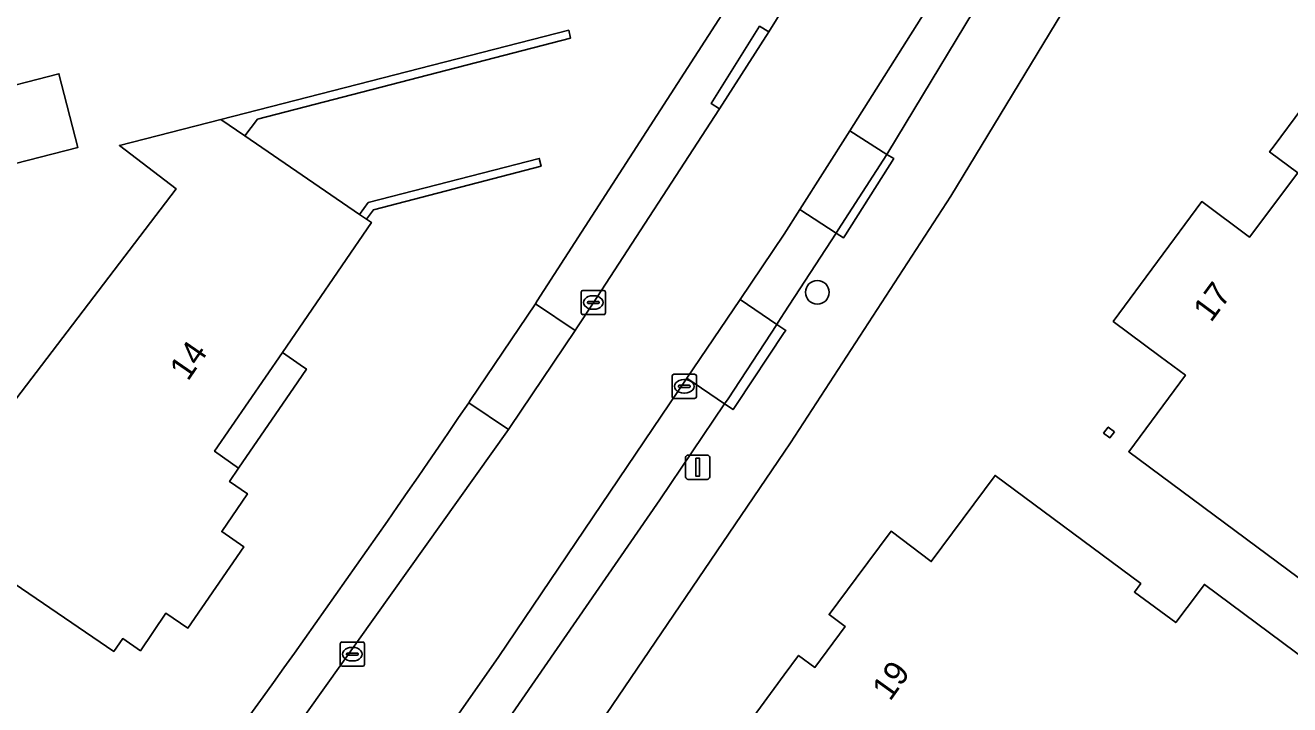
# Model space of a CAD drawing. Extents: x 158835 to 160077, y 386387 to 387778.
# Drawn here: x 159468.8 to 159520.8, y 386661.1 to 386689.1 of the extents above; entities that cross this region are included whole.
import ezdxf

# ---------------------------------------------------------------- set-up
doc = ezdxf.new("R2010")
doc.units = 0
for name, color, linetype in [('IMGEO_Boom', 7, 'Continuous'), ('IMGEO_Erf', 7, 'Continuous'), ('IMGEO_Kolk', 7, 'Continuous'), ('IMGEO_Lichtmast', 7, 'Continuous'), ('IMGEO_Muur', 7, 'Continuous'), ('IMGEO_Pand', 7, 'Continuous'), ('IMGEO_Pand_nummerreeks', 7, 'Continuous'), ('IMGEO_Pand_overbouw', 7, 'Continuous'), ('IMGEO_Parkeervlak_open', 7, 'Continuous'), ('IMGEO_Rijbaan_lokaal_gesloten', 7, 'Continuous'), ('IMGEO_Voetpad_open', 7, 'Continuous')]:
    doc.layers.add(name, color=color, linetype=linetype)

msp = doc.modelspace()

# ---------------------------------------------------------------- linework, layer by layer
at = {"layer": 'IMGEO_Boom'}
msp.add_circle((159501.359, 386678.098), 0.489, dxfattribs=at)
at = {"layer": 'IMGEO_Erf'}
for points in [[(159523.936, 386720.207), (159523.989, 386717.606), (159523.81, 386715.012), (159523.4, 386712.444), (159522.762, 386709.923), (159521.901, 386707.468), (159520.825, 386705.101), (159506.854, 386682.053), (159500.252, 386671.907), (159500, 386671.529), (159492.426, 386660.371), (159492.025, 386659.896), (159480.297, 386643.692), (159466.865, 386626.712)], [(159487.016, 386673.557), (159487.077, 386673.647), (159489.757, 386677.629), (159489.836, 386677.746), (159499.829, 386693.238), (159500, 386693.513), (159510.606, 386711.419), (159511.034, 386712.323), (159511.379, 386713.262), (159511.639, 386714.228), (159511.811, 386715.214), (159511.887, 386716.039), (159511.952, 386719.617)], [(159522.042, 386665.693), (159514.171, 386671.538), (159516.506, 386674.684), (159515.461, 386675.464), (159513.533, 386676.904), (159517.176, 386681.83), (159519.142, 386680.372), (159521.129, 386683.006), (159519.965, 386683.87), (159520.153, 386684.123), (159522.43, 386687.19)], [(159498.048, 386659.711), (159500, 386662.363), (159500.589, 386663.163), (159501.258, 386662.671), (159502.506, 386664.348), (159501.841, 386664.844), (159502.959, 386666.346), (159504.391, 386668.27), (159506.047, 386667.022), (159508.675, 386670.566), (159514.667, 386666.121), (159514.405, 386665.768), (159516.105, 386664.516), (159516.575, 386665.131), (159517.286, 386666.082), (159529.001, 386657.369)]]:
    msp.add_lwpolyline(points, dxfattribs=at)
for points in [[(159472.645, 386684.138), (159476.823, 386685.207), (159491.131, 386688.877), (159491.202, 386688.552), (159478.326, 386685.224), (159477.803, 386684.535), (159482.519, 386681.3), (159482.879, 386681.794), (159489.914, 386683.607), (159489.99, 386683.281), (159483.094, 386681.494), (159482.805, 386681.113), (159483.009, 386680.975), (159479.351, 386675.617), (159476.56, 386671.56), (159477.546, 386670.861), (159477.174, 386670.314), (159477.911, 386669.812), (159476.855, 386668.254), (159477.761, 386667.631), (159475.462, 386664.289), (159474.553, 386664.901), (159473.506, 386663.357), (159472.784, 386663.856), (159472.411, 386663.325), (159464.547, 386668.691), (159474.982, 386682.353)], [(159467.053, 386686.293), (159470.155, 386687.091), (159470.936, 386684.056), (159467.834, 386683.258)], [(159513.582, 386672.364), (159513.396, 386672.113), (159513.138, 386672.305), (159513.325, 386672.556)]]:
    msp.add_lwpolyline(points, close=True, dxfattribs=at)
msp.add_arc((159034.245, 386981.09), 547.337, 323.34107, 325.81472, dxfattribs=at)
at = {"layer": 'IMGEO_Kolk'}
for p, q in [((159491.717, 386678.179), (159492.569, 386678.179)), ((159491.642, 386677.253), (159491.642, 386678.105)), ((159491.901, 386677.673), (159491.901, 386677.685)), ((159492.339, 386677.636), (159491.941, 386677.636)), ((159491.944, 386677.722), (159492.342, 386677.722)), ((159492.13, 386677.959), (159492.155, 386677.959)), ((159492.385, 386677.685), (159492.385, 386677.673)), ((159492.643, 386678.105), (159492.643, 386677.253)), ((159492.569, 386677.179), (159491.717, 386677.179)), ((159492.153, 386677.399), (159492.128, 386677.399)), ((159495.384, 386673.805), (159495.384, 386674.657)), ((159495.459, 386674.731), (159496.311, 386674.731)), ((159495.872, 386674.511), (159495.897, 386674.511)), ((159496.385, 386674.657), (159496.385, 386673.805)), ((159495.643, 386674.225), (159495.643, 386674.237)), ((159496.081, 386674.188), (159495.683, 386674.188)), ((159495.686, 386674.274), (159496.084, 386674.274)), ((159496.127, 386674.237), (159496.127, 386674.225)), ((159496.311, 386673.731), (159495.459, 386673.731)), ((159495.895, 386673.951), (159495.87, 386673.951)), ((159481.727, 386662.789), (159481.727, 386663.641)), ((159481.802, 386663.715), (159482.654, 386663.715)), ((159482.728, 386663.641), (159482.728, 386662.789)), ((159481.986, 386663.209), (159481.986, 386663.221)), ((159482.424, 386663.172), (159482.026, 386663.172)), ((159482.029, 386663.258), (159482.427, 386663.258)), ((159482.215, 386663.495), (159482.24, 386663.495)), ((159482.47, 386663.221), (159482.47, 386663.209)), ((159482.654, 386662.715), (159481.802, 386662.715)), ((159482.238, 386662.935), (159482.213, 386662.935))]:
    msp.add_line(p, q, dxfattribs=at)
for points in [[(159491.717, 386678.179), (159492.569, 386678.179)], [(159491.642, 386677.253), (159491.642, 386678.105)], [(159492.643, 386678.105), (159492.643, 386677.253)], [(159492.569, 386677.179), (159491.717, 386677.179)], [(159495.384, 386673.805), (159495.384, 386674.657)], [(159495.459, 386674.731), (159496.311, 386674.731)], [(159496.385, 386674.657), (159496.385, 386673.805)], [(159496.311, 386673.731), (159495.459, 386673.731)], [(159481.727, 386662.789), (159481.727, 386663.641)], [(159481.802, 386663.715), (159482.654, 386663.715)], [(159482.728, 386663.641), (159482.728, 386662.789)], [(159482.654, 386662.715), (159481.802, 386662.715)]]:
    msp.add_lwpolyline(points, dxfattribs=at)
for centre, radius, start, end in [((159491.719, 386678.103), 0.0765, 91.552, 178.448), ((159491.719, 386678.103), 0.0765, 91.552, 178.448), ((159492.567, 386678.103), 0.0765, 1.552, 88.448), ((159492.567, 386678.103), 0.0765, 1.552, 88.448), ((159491.941, 386677.682), 0.0403, 85.8775, 175.7526), ((159491.938, 386677.672), 0.0366, 178.938, 274.7102), ((159492.342, 386677.679), 0.043, 264.8664, 352.4533), ((159492.346, 386677.684), 0.0386, 1.7309, 96.639), ((159491.719, 386677.255), 0.0765, 181.552, 268.448), ((159491.719, 386677.255), 0.0765, 181.552, 268.448), ((159492.567, 386677.255), 0.0765, 271.552, 358.448), ((159492.567, 386677.255), 0.0765, 271.552, 358.448), ((159495.461, 386674.655), 0.0765, 91.552, 178.448), ((159495.461, 386674.655), 0.0765, 91.552, 178.448), ((159496.309, 386674.655), 0.0765, 1.552, 88.448), ((159496.309, 386674.655), 0.0765, 1.552, 88.448), ((159495.683, 386674.234), 0.0403, 85.8775, 175.7526), ((159495.68, 386674.224), 0.0366, 178.938, 274.7102), ((159496.084, 386674.231), 0.043, 264.8664, 352.4533), ((159496.088, 386674.236), 0.0386, 1.7309, 96.639), ((159495.461, 386673.807), 0.0765, 181.552, 268.448), ((159495.461, 386673.807), 0.0765, 181.552, 268.448), ((159496.309, 386673.807), 0.0765, 271.552, 358.448), ((159496.309, 386673.807), 0.0765, 271.552, 358.448), ((159481.804, 386663.639), 0.0765, 91.552, 178.448), ((159481.804, 386663.639), 0.0765, 91.552, 178.448), ((159482.652, 386663.639), 0.0765, 1.552, 88.448), ((159482.652, 386663.639), 0.0765, 1.552, 88.448), ((159482.026, 386663.218), 0.0403, 85.8775, 175.7526), ((159482.023, 386663.208), 0.0366, 178.938, 274.7102), ((159482.427, 386663.215), 0.043, 264.8664, 352.4533), ((159482.431, 386663.22), 0.0386, 1.7309, 96.639), ((159481.804, 386662.791), 0.0765, 181.552, 268.448), ((159481.804, 386662.791), 0.0765, 181.552, 268.448), ((159482.652, 386662.791), 0.0765, 271.552, 358.448), ((159482.652, 386662.791), 0.0765, 271.552, 358.448)]:
    msp.add_arc(centre, radius, start, end, dxfattribs=at)
for centre, major_axis, ratio, start_param, end_param in [((159492.129, 386677.679), (-0.387, 0.002), 0.722429, 4.712389, 7.853982), ((159492.154, 386677.679), (-0.39, 0.002), 0.717154, 1.570796, 4.712389), ((159495.871, 386674.231), (-0.387, 0.002), 0.722429, 4.712389, 7.853982), ((159495.896, 386674.231), (-0.39, 0.002), 0.717154, 1.570796, 4.712389), ((159482.214, 386663.215), (-0.387, 0.002), 0.722429, 4.712389, 7.853982), ((159482.239, 386663.215), (-0.39, 0.002), 0.717154, 1.570796, 4.712389)]:
    msp.add_ellipse(centre, major_axis=major_axis, ratio=ratio, start_param=start_param, end_param=end_param, dxfattribs=at)
at = {"layer": 'IMGEO_Lichtmast'}
for p, q in [((159496.04, 386671.405), (159496.83, 386671.405)), ((159496.83, 386671.405), (159496.04, 386671.405)), ((159495.94, 386670.505), (159495.94, 386671.305)), ((159495.94, 386671.305), (159495.94, 386670.505)), ((159496.93, 386671.305), (159496.93, 386670.505)), ((159496.93, 386670.505), (159496.93, 386671.305)), ((159496.83, 386670.405), (159496.04, 386670.405)), ((159496.04, 386670.405), (159496.83, 386670.405))]:
    msp.add_line(p, q, dxfattribs=at)
msp.add_lwpolyline([(159496.36, 386671.28), (159496.51, 386671.28), (159496.51, 386670.53), (159496.36, 386670.53), (159496.36, 386671.28)], dxfattribs=at)
for centre, start, end in [((159496.04, 386671.305), 90, 180), ((159496.04, 386671.305), 90, 180), ((159496.83, 386671.305), 0, 90), ((159496.83, 386671.305), 360, 90), ((159496.04, 386670.505), 180, 270), ((159496.04, 386670.505), 180, 270), ((159496.83, 386670.505), 270, 0), ((159496.83, 386670.505), 270, 0)]:
    msp.add_arc(centre, 0.1, start, end, dxfattribs=at)
at = {"layer": 'IMGEO_Muur'}
for points in [[(159477.803, 386684.535), (159478.326, 386685.224), (159491.202, 386688.552), (159491.131, 386688.877), (159476.823, 386685.207)], [(159482.805, 386681.113), (159483.094, 386681.494), (159489.99, 386683.281), (159489.914, 386683.607), (159482.879, 386681.794), (159482.519, 386681.3)]]:
    msp.add_lwpolyline(points, close=True, dxfattribs=at)
at = {"layer": 'IMGEO_Pand'}
for points in [[(159467.053, 386686.293), (159467.834, 386683.258), (159470.936, 386684.056), (159470.155, 386687.091)], [(159522.43, 386687.19), (159520.153, 386684.123), (159519.965, 386683.87), (159521.129, 386683.006), (159519.142, 386680.372), (159517.176, 386681.83), (159513.533, 386676.904), (159515.461, 386675.464), (159516.506, 386674.684), (159514.171, 386671.538), (159522.042, 386665.693), (159525.422, 386670.2), (159523.707, 386671.486), (159527.613, 386676.695), (159533.54, 386672.251), (159529.173, 386666.427), (159533.385, 386663.269), (159540.934, 386673.397)], [(159483.009, 386680.975), (159482.805, 386681.113), (159482.519, 386681.3), (159477.803, 386684.535), (159476.823, 386685.207), (159472.645, 386684.138), (159474.982, 386682.353), (159464.547, 386668.691), (159472.411, 386663.325), (159472.784, 386663.856), (159473.506, 386663.357), (159474.553, 386664.901), (159475.462, 386664.289), (159477.761, 386667.631), (159476.855, 386668.254), (159477.911, 386669.812), (159477.174, 386670.314), (159477.546, 386670.861), (159476.56, 386671.56), (159479.351, 386675.617)], [(159513.582, 386672.364), (159513.325, 386672.556), (159513.138, 386672.305), (159513.396, 386672.113)]]:
    msp.add_lwpolyline(points, close=True, dxfattribs=at)
msp.add_lwpolyline([(159529.001, 386657.369), (159517.286, 386666.082), (159516.575, 386665.131), (159516.105, 386664.516), (159514.405, 386665.768), (159514.667, 386666.121), (159508.675, 386670.566), (159506.047, 386667.022), (159504.391, 386668.27), (159502.959, 386666.346), (159501.841, 386664.844), (159502.506, 386664.348), (159501.258, 386662.671), (159500.589, 386663.163), (159500, 386662.363), (159498.048, 386659.711)], dxfattribs=at)
at = {"layer": 'IMGEO_Pand_overbouw'}
msp.add_lwpolyline([(159477.546, 386670.861), (159479.98, 386674.411), (159480.341, 386674.941), (159480.078, 386675.12), (159479.351, 386675.617), (159476.56, 386671.56)], close=True, dxfattribs=at)
at = {"layer": 'IMGEO_Parkeervlak_open'}
for points in [[(159518.046, 386706.634), (159519.101, 386708.953), (159517.443, 386709.606), (159517.076, 386708.722), (159516.302, 386707.245), (159505.787, 386689.619), (159502.694, 386684.743), (159504.222, 386683.773), (159504.259, 386683.831)], [(159502.136, 386680.535), (159500.64, 386681.505), (159500, 386680.496), (159498.178, 386677.802), (159499.693, 386676.778), (159499.749, 386676.864), (159500, 386677.248)], [(159497.546, 386673.509), (159495.988, 386674.563), (159488.253, 386663.123), (159486.494, 386660.609), (159487.977, 386659.57), (159488.022, 386659.633), (159494.875, 386669.563)]]:
    msp.add_lwpolyline(points, close=True, dxfattribs=at)
at = {"layer": 'IMGEO_Rijbaan_lokaal_gesloten'}
for points in [[(159513.878, 386721.278), (159513.869, 386716.038), (159513.796, 386715.241), (159513.584, 386713.955), (159513.258, 386712.692), (159512.821, 386711.465), (159512.275, 386710.281), (159511.626, 386709.15), (159501.61, 386692.371), (159500.806, 386691.095), (159500, 386689.822), (159499.36, 386688.811), (159497.335, 386685.65), (159492.103, 386677.614), (159491.469, 386676.644), (159491.393, 386676.531), (159488.703, 386672.537), (159488.647, 386672.459), (159474.87, 386653.114), (159472.629, 386650.095), (159472.496, 386649.912), (159463.597, 386638.445)], [(159465.699, 386633.096), (159473.919, 386643.589), (159475.879, 386646.09), (159476.255, 386646.598), (159484.227, 386657.37), (159484.364, 386657.566), (159486.494, 386660.609), (159488.253, 386663.123), (159495.988, 386674.563), (159498.178, 386677.802), (159500, 386680.496), (159500.64, 386681.505), (159502.694, 386684.743), (159505.787, 386689.619), (159516.302, 386707.245), (159517.076, 386708.722), (159517.443, 386709.606), (159517.715, 386710.261), (159518.213, 386711.852), (159518.439, 386712.887), (159518.568, 386713.481), (159518.776, 386715.135), (159518.834, 386716.37), (159518.864, 386721.239)]]:
    msp.add_lwpolyline(points, dxfattribs=at)
at = {"layer": 'IMGEO_Voetpad_open'}
for points in [[(159452.919, 386610.024), (159466.865, 386626.712), (159480.297, 386643.692), (159492.025, 386659.896), (159492.426, 386660.371), (159500, 386671.529), (159500.252, 386671.907), (159506.854, 386682.053), (159520.825, 386705.101), (159521.901, 386707.468), (159522.762, 386709.923), (159523.4, 386712.444), (159523.81, 386715.012), (159523.989, 386717.606), (159523.936, 386720.207), (159523.829, 386721.437), (159523.607, 386726.844), (159524.846, 386728.532), (159523.605, 386733.299), (159523.378, 386733.241)], [(159518.046, 386706.634), (159504.259, 386683.831), (159504.222, 386683.773), (159504.501, 386683.596), (159502.515, 386680.466), (159502.436, 386680.341), (159502.136, 386680.535), (159500, 386677.248), (159499.749, 386676.864), (159499.693, 386676.778), (159500.056, 386676.532), (159500, 386676.448), (159498.039, 386673.485), (159497.895, 386673.272), (159497.546, 386673.509), (159494.875, 386669.563), (159488.022, 386659.633)], [(159499.829, 386693.238), (159489.836, 386677.746), (159489.757, 386677.629), (159491.393, 386676.531), (159491.469, 386676.644), (159492.103, 386677.614), (159497.335, 386685.65), (159496.984, 386685.866), (159498.981, 386689.045), (159499.36, 386688.811), (159500, 386689.822)], [(159434.001, 386603.754), (159434.251, 386604.023), (159438.438, 386608.651), (159445.723, 386616.887), (159445.368, 386617.173), (159447.821, 386620.028), (159448.174, 386619.761), (159449.947, 386621.841), (159460.729, 386634.881), (159460.383, 386635.173), (159462.739, 386638.108), (159463.101, 386637.845), (159463.597, 386638.445), (159472.496, 386649.912), (159472.629, 386650.095), (159472.275, 386650.344), (159474.5, 386653.37), (159474.87, 386653.114), (159488.647, 386672.459), (159487.016, 386673.557)]]:
    msp.add_lwpolyline(points, dxfattribs=at)
for points in [[(159497.335, 386685.65), (159499.36, 386688.811), (159498.981, 386689.045), (159496.984, 386685.866)], [(159504.222, 386683.773), (159502.694, 386684.743), (159500.64, 386681.505), (159502.136, 386680.535), (159502.22, 386680.664)], [(159504.501, 386683.596), (159504.222, 386683.773), (159502.22, 386680.664), (159502.136, 386680.535), (159502.436, 386680.341), (159502.515, 386680.466)], [(159499.693, 386676.778), (159498.178, 386677.802), (159495.988, 386674.563), (159497.546, 386673.509), (159497.688, 386673.719)], [(159491.393, 386676.531), (159489.757, 386677.629), (159487.077, 386673.647), (159487.016, 386673.557), (159488.647, 386672.459), (159488.703, 386672.537)], [(159500, 386676.448), (159500.056, 386676.532), (159499.693, 386676.778), (159497.688, 386673.719), (159497.546, 386673.509), (159497.895, 386673.272), (159498.039, 386673.485)]]:
    msp.add_lwpolyline(points, close=True, dxfattribs=at)
msp.add_arc((159034.245, 386981.09), 547.337, 323.34107, 325.81472, dxfattribs=at)

# ---------------------------------------------------------------- texts
at = {"layer": 'IMGEO_Pand_nummerreeks'}
for s, rotation, p in [('17', 53.5143, (159517.554, 386676.826)), ('14', 55.4741, (159475.462, 386674.411)), ('19', 54.42, (159504.351, 386661.247))]:
    msp.add_text(s, height=1, rotation=rotation, dxfattribs=at).set_placement(p)

doc.saveas('drawing.dxf')
